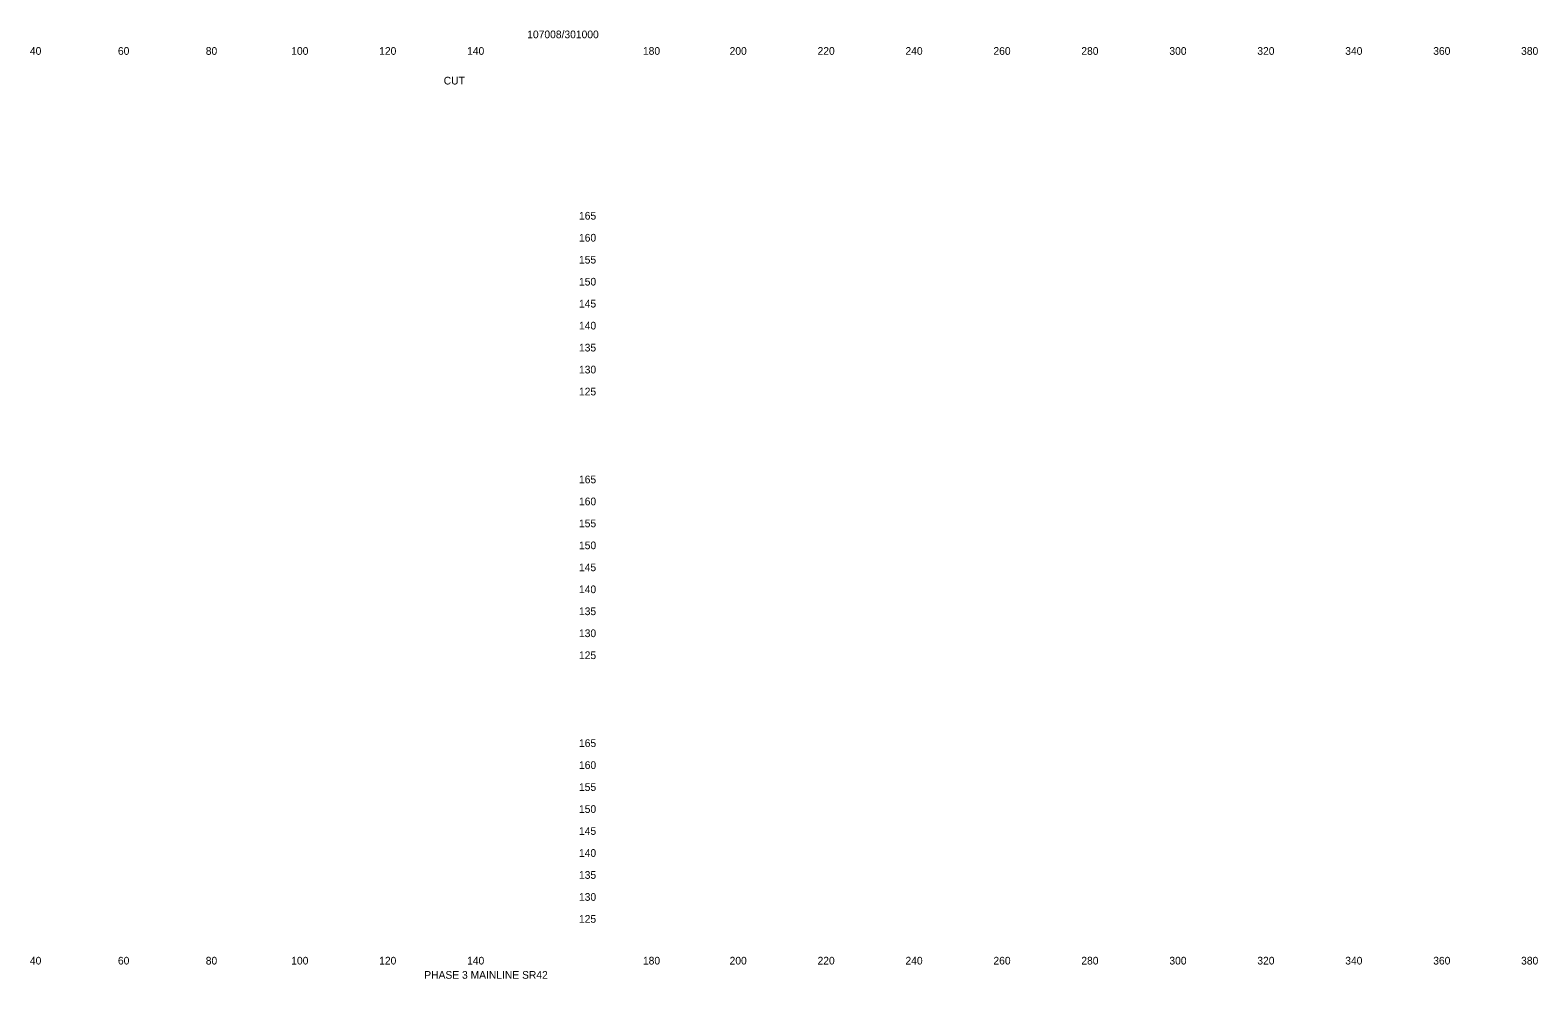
# Model space of a CAD drawing. Extents: x 21281 to 22024, y 6472 to 6918.
# Drawn here: x 21681.3 to 22024.2, y 6472.1 to 6688 of the extents above; entities that cross this region are included whole.
import ezdxf

# ---------------------------------------------------------------- set-up
doc = ezdxf.new("R2010")
doc.units = 0
doc.layers.add('XS_SHEET_EW_TX_VOLUME', color=7, linetype='Continuous')
doc.layers.add('XS_SHEET_LABELS_OFFSET', color=7, linetype='Continuous')

msp = doc.modelspace()

# ---------------------------------------------------------------- texts
at = {"layer": 'XS_SHEET_EW_TX_VOLUME'}
for s, p in [('107008/301000', (21794.37, 6686.11)), ('  40  ', (21679.95, 6682.34)), ('  60  ', (21699.97, 6682.34)), ('  80  ', (21719.95, 6682.34)), ('  100  ', (21739.39, 6682.34)), ('  120  ', (21759.39, 6682.34)), ('  140  ', (21779.39, 6682.34)), ('CUT', (21775.37, 6675.59)), ('  165  ', (21804.84, 6644.84)), ('  160  ', (21804.84, 6639.84)), ('  155  ', (21804.84, 6634.84)), ('  150  ', (21804.84, 6629.84)), ('  145  ', (21804.84, 6624.84)), ('  140  ', (21804.84, 6619.84)), ('  135  ', (21804.84, 6614.84)), ('  130  ', (21804.84, 6609.84)), ('  125  ', (21804.84, 6604.84)), ('  165  ', (21804.84, 6584.84)), ('  160  ', (21804.84, 6579.84)), ('  155  ', (21804.84, 6574.84)), ('  150  ', (21804.84, 6569.84)), ('  145  ', (21804.84, 6564.84)), ('  140  ', (21804.84, 6559.84)), ('  135  ', (21804.84, 6554.84)), ('  130  ', (21804.84, 6549.84)), ('  125  ', (21804.84, 6544.84)), ('  165  ', (21804.84, 6524.84)), ('  160  ', (21804.84, 6519.84)), ('  155  ', (21804.84, 6514.84)), ('  150  ', (21804.84, 6509.84)), ('  145  ', (21804.84, 6504.84)), ('  140  ', (21804.84, 6499.84)), ('  135  ', (21804.84, 6494.84)), ('  130  ', (21804.84, 6489.84)), ('  125  ', (21804.84, 6484.84)), ('  40  ', (21679.95, 6475.34)), ('  60  ', (21699.97, 6475.34)), ('  80  ', (21719.95, 6475.34)), ('  100  ', (21739.39, 6475.34)), ('  120  ', (21759.39, 6475.34)), ('  140  ', (21779.39, 6475.34)), ('PHASE 3 MAINLINE SR42', (21770.95, 6472.1))]:
    msp.add_text(s, height=1.75, dxfattribs=at).set_placement(p)
at = {"layer": 'XS_SHEET_LABELS_OFFSET'}
for s, p in [('  180  ', (21819.39, 6682.34)), ('  200  ', (21839.1, 6682.34)), ('  220  ', (21859.1, 6682.34)), ('  240  ', (21879.1, 6682.34)), ('  260  ', (21899.11, 6682.34)), ('  280  ', (21919.1, 6682.34)), ('  300  ', (21939.13, 6682.34)), ('  320  ', (21959.13, 6682.34)), ('  340  ', (21979.13, 6682.34)), ('  360  ', (21999.14, 6682.34)), ('  380  ', (22019.13, 6682.34)), ('  180  ', (21819.39, 6475.34)), ('  200  ', (21839.1, 6475.34)), ('  220  ', (21859.1, 6475.34)), ('  240  ', (21879.1, 6475.34)), ('  260  ', (21899.11, 6475.34)), ('  280  ', (21919.1, 6475.34)), ('  300  ', (21939.13, 6475.34)), ('  320  ', (21959.13, 6475.34)), ('  340  ', (21979.13, 6475.34)), ('  360  ', (21999.14, 6475.34)), ('  380  ', (22019.13, 6475.34))]:
    msp.add_text(s, height=1.75, dxfattribs=at).set_placement(p)

doc.saveas('drawing.dxf')
